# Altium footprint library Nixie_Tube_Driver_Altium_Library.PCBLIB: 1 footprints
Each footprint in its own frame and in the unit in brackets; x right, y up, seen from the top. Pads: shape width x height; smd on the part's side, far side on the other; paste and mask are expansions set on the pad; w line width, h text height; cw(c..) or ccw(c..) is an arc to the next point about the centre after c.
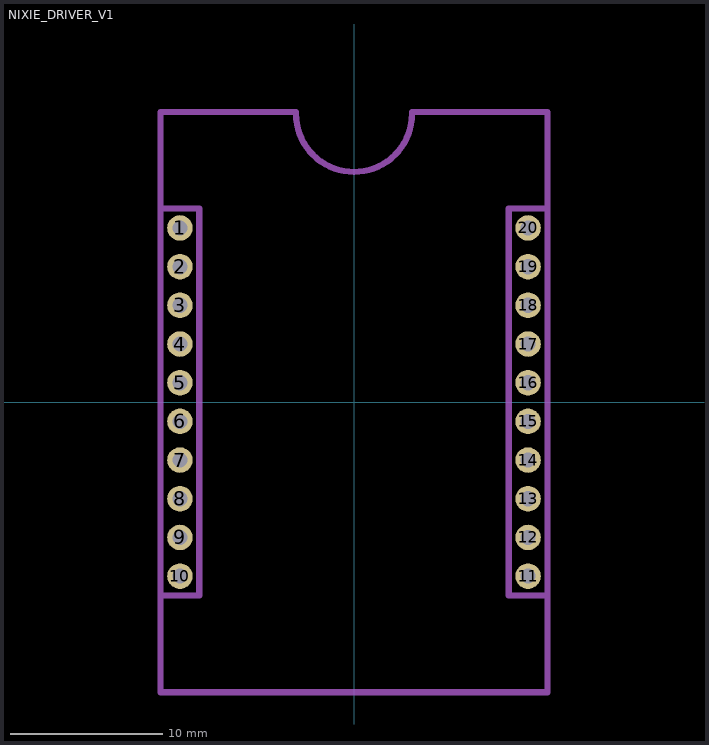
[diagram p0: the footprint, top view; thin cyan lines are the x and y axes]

## NIXIE_DRIVER_V1 [mil] "www.NixieTester.com"
pads (20):
  round 66 / inner round 60 / far side round 66 hole 39.37: 1(-450,450) 2(-450,350) 3(-450,250) 4(-450,150) 5(-450,50) 6(-450,-50) 7(-450,-150) 8(-450,-250) 9(-450,-350) 10(-450,-450) 11(450,-450) 12(450,-350) 13(450,-250) 14(450,-150) 15(450,-50) 16(450,50) 17(450,150) 18(450,250) 19(450,350) 20(450,450)
Assembly Top:
  lines w16: -150,745 ccw(c0,745) 150,745 ; -150,750 -500,750 -500,500 ; 150,750 500,750 500,500 ; -500,-500 -400,-500 -400,500 -500,500 ; -500,-500 -500,500 ; -500,-500 -500,-750 500,-750 500,-500 ; 500,-500 400,-500 400,500 500,500 ; 500,-500 500,500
